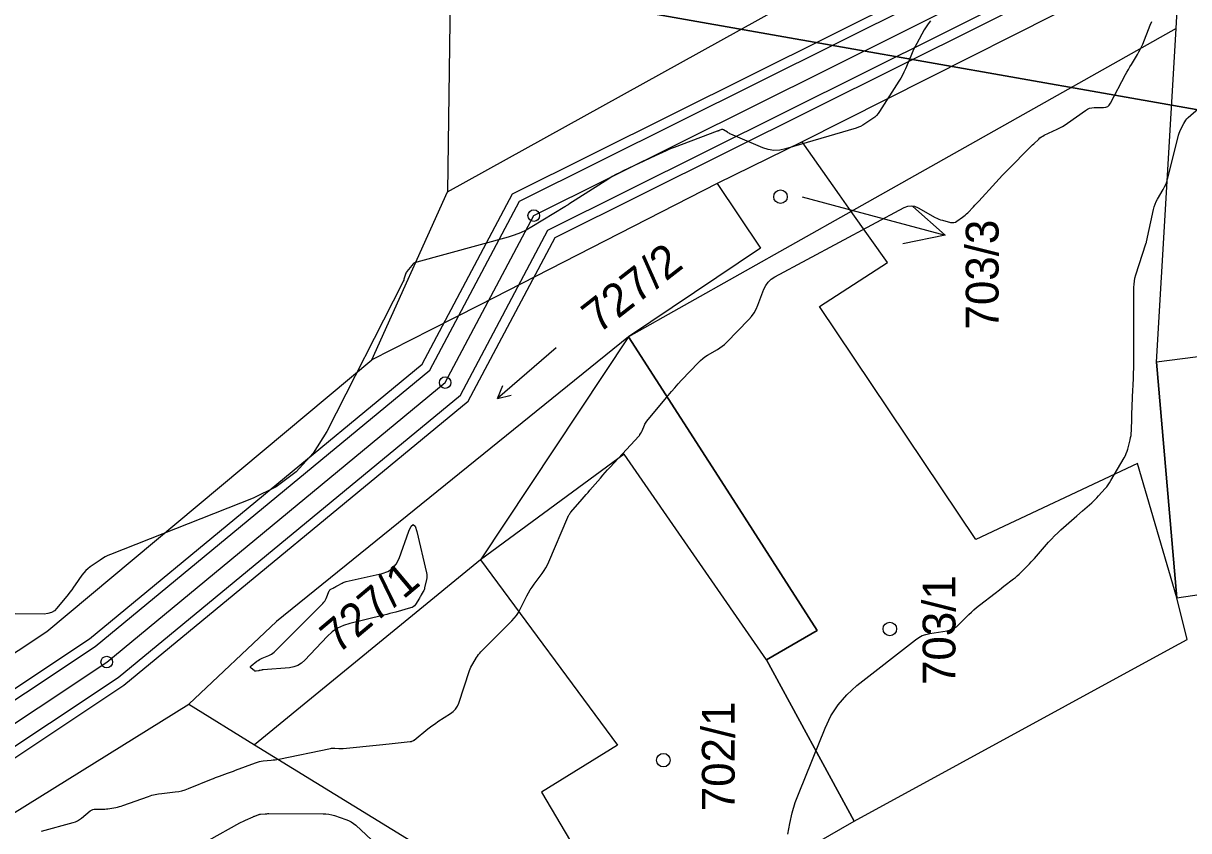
# Model space of a CAD drawing. Extents: x -534481 to -534256, y -1190577 to -1190138.
# Drawn here: x -534395.86 to -534365.66, y -1190377.09 to -1190356.16 of the extents above; entities that cross this region are included whole.
import ezdxf

# ---------------------------------------------------------------- set-up
doc = ezdxf.new("R2010")
doc.units = 0
for name, color, linetype in [('0_kroužky', 7, 'Continuous'), ('30', 7, 'Continuous'), ('31', 7, 'Continuous'), ('_N_osa', 7, 'Continuous'), ('_N_tenká', 7, 'Continuous'), ('_rámeček', 7, 'Continuous'), ('Hranice parcel', 7, 'Continuous'), ('Parcelní čísla', 7, 'Continuous'), ('Polygon budovy', 7, 'Continuous'), ('Pop  PČ popisy', 7, 'Continuous'), ('Značky budov', 7, 'Continuous'), ('Značky kultur', 7, 'Continuous')]:
    doc.layers.add(name, color=color, linetype=linetype)

msp = doc.modelspace()

# ---------------------------------------------------------------- linework, layer by layer
at = {"layer": '0_kroužky'}
for centre in [(-534382.631, -1190361.148), (-534382.631, -1190361.148), (-534382.631, -1190361.148), (-534382.631, -1190361.148), (-534382.631, -1190361.148), (-534382.631, -1190361.148), (-534384.927, -1190365.477), (-534384.927, -1190365.477), (-534384.927, -1190365.477), (-534384.927, -1190365.477), (-534384.927, -1190365.477), (-534384.927, -1190365.477), (-534393.696, -1190372.718), (-534393.696, -1190372.718), (-534393.696, -1190372.718), (-534393.696, -1190372.718), (-534393.696, -1190372.718), (-534393.696, -1190372.718)]:
    msp.add_circle(centre, 0.15, dxfattribs=at)
at = {"layer": '30'}
for points in [[(-534376.046, -1190377.175), (-534375.999, -1190376.898), (-534375.936, -1190376.627), (-534375.856, -1190376.36), (-534375.759, -1190376.097), (-534375.084, -1190374.43), (-534374.933, -1190374.114), (-534374.744, -1190373.825), (-534374.519, -1190373.564), (-534374.257, -1190373.33), (-534372.744, -1190372.141), (-534372.658, -1190372.081), (-534372.567, -1190372.034), (-534372.471, -1190372), (-534372.369, -1190371.977), (-534371.924, -1190371.906), (-534371.837, -1190371.886), (-534371.756, -1190371.852), (-534371.682, -1190371.807), (-534371.615, -1190371.748), (-534371.358, -1190371.488), (-534371.292, -1190371.424), (-534371.225, -1190371.363), (-534371.156, -1190371.304), (-534371.085, -1190371.247), (-534370.679, -1190370.934), (-534370.563, -1190370.845), (-534370.448, -1190370.755), (-534370.201, -1190370.565), (-534370.151, -1190370.525), (-534370.103, -1190370.484), (-534370.056, -1190370.441), (-534370.011, -1190370.397), (-534369.832, -1190370.217), (-534369.788, -1190370.171), (-534369.744, -1190370.125), (-534369.701, -1190370.078), (-534369.659, -1190370.031), (-534369.293, -1190369.615), (-534369.216, -1190369.531), (-534369.138, -1190369.45), (-534369.056, -1190369.371), (-534368.972, -1190369.295), (-534368.557, -1190368.929), (-534368.414, -1190368.802), (-534368.175, -1190368.592), (-534368.128, -1190368.549), (-534368.082, -1190368.505), (-534368.038, -1190368.46), (-534367.995, -1190368.413), (-534367.827, -1190368.222), (-534367.786, -1190368.173), (-534367.748, -1190368.123), (-534367.712, -1190368.07), (-534367.679, -1190368.016), (-534367.332, -1190367.422), (-534367.303, -1190367.369), (-534367.279, -1190367.314), (-534367.258, -1190367.257), (-534367.24, -1190367.199), (-534367.18, -1190366.963), (-534367.166, -1190366.903), (-534367.156, -1190366.844), (-534367.15, -1190366.783), (-534367.146, -1190366.723), (-534367.138, -1190366.388), (-534367.136, -1190366.312), (-534367.133, -1190366.236), (-534367.13, -1190366.16), (-534367.127, -1190366.084), (-534367.105, -1190365.651), (-534367.102, -1190365.571), (-534367.099, -1190365.49), (-534367.096, -1190365.409), (-534367.094, -1190365.329), (-534367.086, -1190365.006), (-534367.084, -1190364.925), (-534367.083, -1190364.844), (-534367.082, -1190364.764), (-534367.082, -1190364.683), (-534367.082, -1190364.349), (-534367.082, -1190364.184), (-534367.082, -1190364.018), (-534367.082, -1190363.671), (-534367.082, -1190363.505), (-534367.082, -1190363.34), (-534367.082, -1190363.01), (-534367.079, -1190362.928), (-534367.069, -1190362.846), (-534367.054, -1190362.766), (-534367.032, -1190362.687), (-534366.773, -1190361.881), (-534366.77, -1190361.872), (-534366.766, -1190361.862), (-534366.757, -1190361.844), (-534366.755, -1190361.839), (-534366.754, -1190361.834), (-534366.752, -1190361.829), (-534366.751, -1190361.825), (-534366.573, -1190360.987), (-534366.555, -1190360.917), (-534366.532, -1190360.849), (-534366.503, -1190360.783), (-534366.469, -1190360.719), (-534366.32, -1190360.468), (-534366.285, -1190360.404), (-534366.255, -1190360.338), (-534366.23, -1190360.27), (-534366.21, -1190360.2), (-534365.935, -1190359.106), (-534365.922, -1190359.06), (-534365.907, -1190359.015), (-534365.89, -1190358.971), (-534365.87, -1190358.928), (-534365.785, -1190358.757), (-534365.762, -1190358.716), (-534365.736, -1190358.678), (-534365.706, -1190358.642), (-534365.672, -1190358.609), (-534365.014, -1190358.03)], [(-534391.053, -1190377.337), (-534390.246, -1190376.885), (-534390.21, -1190376.865), (-534390.173, -1190376.846), (-534390.136, -1190376.829), (-534390.099, -1190376.812), (-534389.905, -1190376.728), (-534389.889, -1190376.721), (-534389.873, -1190376.715), (-534389.857, -1190376.708), (-534389.841, -1190376.702), (-534389.776, -1190376.678), (-534389.759, -1190376.672), (-534389.743, -1190376.667), (-534389.726, -1190376.664), (-534389.708, -1190376.662), (-534389.595, -1190376.651), (-534389.57, -1190376.649), (-534389.545, -1190376.648), (-534389.52, -1190376.647), (-534389.496, -1190376.647), (-534388.092, -1190376.649), (-534388.016, -1190376.652), (-534387.941, -1190376.661), (-534387.866, -1190376.676), (-534387.793, -1190376.698), (-534387.502, -1190376.796), (-534387.431, -1190376.824), (-534387.364, -1190376.858), (-534387.302, -1190376.9), (-534387.243, -1190376.949), (-534386.709, -1190377.445)]]:
    msp.add_lwpolyline(points, dxfattribs=at)
msp.add_lwpolyline([(-534386.285, -1190371.443), (-534386.363, -1190371.463), (-534386.441, -1190371.483), (-534386.519, -1190371.502), (-534387.398, -1190371.715), (-534387.564, -1190371.768), (-534387.718, -1190371.842), (-534387.858, -1190371.939), (-534387.986, -1190372.057), (-534388.565, -1190372.673), (-534388.651, -1190372.749), (-534388.745, -1190372.806), (-534388.849, -1190372.845), (-534388.961, -1190372.864), (-534389.646, -1190372.92), (-534389.656, -1190372.921), (-534389.665, -1190372.923), (-534389.675, -1190372.925), (-534389.685, -1190372.927), (-534389.724, -1190372.936), (-534389.733, -1190372.938), (-534389.743, -1190372.94), (-534389.753, -1190372.942), (-534389.763, -1190372.944), (-534389.828, -1190372.954), (-534389.842, -1190372.955), (-534389.855, -1190372.952), (-534389.867, -1190372.947), (-534389.879, -1190372.939), (-534389.955, -1190372.873), (-534389.967, -1190372.859), (-534389.971, -1190372.845), (-534389.967, -1190372.831), (-534389.954, -1190372.817), (-534389.804, -1190372.698), (-534389.773, -1190372.675), (-534389.74, -1190372.654), (-534389.706, -1190372.636), (-534389.67, -1190372.62), (-534389.5, -1190372.552), (-534389.46, -1190372.534), (-534389.423, -1190372.512), (-534389.389, -1190372.487), (-534389.357, -1190372.458), (-534388.098, -1190371.2), (-534388.071, -1190371.17), (-534388.048, -1190371.138), (-534388.027, -1190371.104), (-534388.01, -1190371.068), (-534387.93, -1190370.875), (-534387.923, -1190370.861), (-534387.913, -1190370.848), (-534387.902, -1190370.838), (-534387.888, -1190370.83), (-534387.816, -1190370.794), (-534387.808, -1190370.79), (-534387.801, -1190370.786), (-534387.794, -1190370.782), (-534387.786, -1190370.778), (-534387.758, -1190370.761), (-534387.743, -1190370.752), (-534387.728, -1190370.744), (-534387.593, -1190370.671), (-534387.568, -1190370.659), (-534387.542, -1190370.648), (-534387.515, -1190370.639), (-534387.488, -1190370.632), (-534386.563, -1190370.425), (-534386.413, -1190370.373), (-534386.289, -1190370.291), (-534386.193, -1190370.179), (-534386.123, -1190370.037), (-534385.866, -1190369.322), (-534385.807, -1190369.194), (-534385.753, -1190369.153), (-534385.705, -1190369.2), (-534385.661, -1190369.334), (-534385.413, -1190370.407), (-534385.405, -1190370.451), (-534385.403, -1190370.494), (-534385.405, -1190370.538), (-534385.412, -1190370.582), (-534385.459, -1190370.796), (-534385.465, -1190370.82), (-534385.473, -1190370.843), (-534385.483, -1190370.866), (-534385.495, -1190370.888), (-534385.545, -1190370.974), (-534385.558, -1190370.996), (-534385.57, -1190371.017), (-534385.583, -1190371.039), (-534385.596, -1190371.06), (-534385.7, -1190371.226), (-534385.724, -1190371.258), (-534385.752, -1190371.284), (-534385.785, -1190371.303), (-534385.822, -1190371.317), (-534386.208, -1190371.422)], close=True, dxfattribs=at)
at = {"layer": '31'}
for points in [[(-534372.349, -1190356.102), (-534372.408, -1190356.177), (-534372.463, -1190356.256), (-534372.512, -1190356.338), (-534372.706, -1190356.686), (-534372.749, -1190356.766), (-534372.789, -1190356.847), (-534372.828, -1190356.929), (-534372.864, -1190357.012), (-534373.003, -1190357.347), (-534373.04, -1190357.43), (-534373.08, -1190357.511), (-534373.124, -1190357.59), (-534373.171, -1190357.667), (-534373.675, -1190358.453), (-534373.711, -1190358.504), (-534373.752, -1190358.55), (-534373.797, -1190358.593), (-534373.847, -1190358.631), (-534374.055, -1190358.773), (-534374.109, -1190358.807), (-534374.164, -1190358.836), (-534374.221, -1190358.86), (-534374.281, -1190358.88), (-534376.108, -1190359.422), (-534376.258, -1190359.453), (-534376.407, -1190359.458), (-534376.554, -1190359.436), (-534376.7, -1190359.388), (-534377.524, -1190359.037), (-534377.547, -1190359.027), (-534377.57, -1190359.015), (-534377.592, -1190359.003), (-534377.614, -1190358.99), (-534377.718, -1190358.923), (-534377.731, -1190358.917), (-534377.744, -1190358.915), (-534377.757, -1190358.915), (-534377.77, -1190358.919), (-534377.824, -1190358.941), (-534377.838, -1190358.947), (-534377.851, -1190358.952), (-534377.865, -1190358.958), (-534377.879, -1190358.963), (-534378.994, -1190359.382), (-534379.071, -1190359.411), (-534379.147, -1190359.443), (-534379.222, -1190359.475), (-534379.297, -1190359.51), (-534379.594, -1190359.651), (-534379.669, -1190359.686), (-534379.743, -1190359.721), (-534379.818, -1190359.756), (-534379.892, -1190359.791), (-534380.317, -1190359.99), (-534380.412, -1190360.036), (-534380.505, -1190360.085), (-534380.597, -1190360.137), (-534380.687, -1190360.192), (-534381.726, -1190360.854), (-534381.735, -1190360.859), (-534381.743, -1190360.865), (-534381.751, -1190360.87), (-534381.76, -1190360.876), (-534381.793, -1190360.899), (-534381.801, -1190360.905), (-534381.81, -1190360.911), (-534381.818, -1190360.916), (-534381.827, -1190360.921), (-534382.679, -1190361.441), (-534382.827, -1190361.524), (-534382.979, -1190361.597), (-534383.135, -1190361.658), (-534383.297, -1190361.708), (-534385.662, -1190362.352), (-534385.701, -1190362.366), (-534385.736, -1190362.385), (-534385.767, -1190362.41), (-534385.795, -1190362.44), (-534385.917, -1190362.595), (-534385.933, -1190362.617), (-534385.946, -1190362.639), (-534385.957, -1190362.664), (-534385.965, -1190362.689), (-534385.995, -1190362.793), (-534386.002, -1190362.818), (-534386.012, -1190362.844), (-534386.022, -1190362.868), (-534386.034, -1190362.892), (-534387.997, -1190366.74), (-534388.35, -1190367.307), (-534388.786, -1190367.785), (-534389.303, -1190368.173), (-534389.902, -1190368.47), (-534393.6, -1190369.929), (-534393.67, -1190369.959), (-534393.739, -1190369.993), (-534393.805, -1190370.032), (-534393.869, -1190370.074), (-534394.122, -1190370.251), (-534394.183, -1190370.298), (-534394.239, -1190370.349), (-534394.29, -1190370.405), (-534394.337, -1190370.466), (-534394.514, -1190370.718), (-534394.558, -1190370.781), (-534394.604, -1190370.843), (-534394.651, -1190370.904), (-534394.699, -1190370.964), (-534394.985, -1190371.318), (-534395.053, -1190371.387), (-534395.131, -1190371.436), (-534395.218, -1190371.464), (-534395.315, -1190371.473), (-534405.894, -1190371.358)], [(-534395.39, -1190377.105), (-534394.568, -1190376.878), (-534394.509, -1190376.858), (-534394.453, -1190376.833), (-534394.401, -1190376.802), (-534394.351, -1190376.765), (-534394.123, -1190376.577), (-534394.091, -1190376.555), (-534394.057, -1190376.539), (-534394.02, -1190376.53), (-534393.982, -1190376.528), (-534393.823, -1190376.531), (-534393.783, -1190376.531), (-534393.743, -1190376.529), (-534393.704, -1190376.525), (-534393.665, -1190376.519), (-534393.462, -1190376.485), (-534393.415, -1190376.476), (-534393.369, -1190376.465), (-534393.323, -1190376.452), (-534393.278, -1190376.437), (-534392.614, -1190376.2), (-534392.53, -1190376.172), (-534392.445, -1190376.15), (-534392.359, -1190376.133), (-534392.271, -1190376.121), (-534391.919, -1190376.084), (-534391.832, -1190376.071), (-534391.746, -1190376.053), (-534391.662, -1190376.029), (-534391.579, -1190375.998), (-534390.979, -1190375.752), (-534390.928, -1190375.732), (-534390.877, -1190375.712), (-534390.825, -1190375.692), (-534390.773, -1190375.674), (-534390.565, -1190375.6), (-534390.513, -1190375.581), (-534390.461, -1190375.562), (-534390.41, -1190375.543), (-534390.358, -1190375.524), (-534389.839, -1190375.327), (-534389.791, -1190375.31), (-534389.742, -1190375.297), (-534389.692, -1190375.287), (-534389.641, -1190375.281), (-534389.437, -1190375.262), (-534389.386, -1190375.256), (-534389.336, -1190375.249), (-534389.285, -1190375.241), (-534389.235, -1190375.232), (-534387.895, -1190374.955), (-534387.869, -1190374.95), (-534387.842, -1190374.948), (-534387.815, -1190374.947), (-534387.788, -1190374.948), (-534387.68, -1190374.957), (-534387.653, -1190374.958), (-534387.627, -1190374.959), (-534387.6, -1190374.958), (-534387.573, -1190374.956), (-534386.626, -1190374.861), (-534386.544, -1190374.853), (-534386.463, -1190374.844), (-534386.382, -1190374.836), (-534386.3, -1190374.827), (-534385.83, -1190374.778), (-534385.821, -1190374.777), (-534385.812, -1190374.775), (-534385.803, -1190374.773), (-534385.794, -1190374.77), (-534385.76, -1190374.758), (-534385.752, -1190374.754), (-534385.744, -1190374.75), (-534385.736, -1190374.746), (-534385.729, -1190374.74), (-534385.372, -1190374.45), (-534385.309, -1190374.401), (-534385.245, -1190374.353), (-534385.18, -1190374.307), (-534385.114, -1190374.263), (-534384.787, -1190374.053), (-534384.716, -1190373.999), (-534384.657, -1190373.936), (-534384.61, -1190373.863), (-534384.575, -1190373.781), (-534384.293, -1190372.934), (-534384.276, -1190372.89), (-534384.258, -1190372.847), (-534384.237, -1190372.805), (-534384.213, -1190372.764), (-534384.115, -1190372.603), (-534384.089, -1190372.563), (-534384.061, -1190372.526), (-534384.031, -1190372.49), (-534383.999, -1190372.455), (-534383.202, -1190371.652), (-534383.139, -1190371.583), (-534383.081, -1190371.51), (-534383.03, -1190371.432), (-534382.984, -1190371.35), (-534382.807, -1190371.001), (-534382.766, -1190370.924), (-534382.722, -1190370.848), (-534382.674, -1190370.775), (-534382.623, -1190370.703), (-534382.414, -1190370.42), (-534382.364, -1190370.348), (-534382.318, -1190370.273), (-534382.277, -1190370.196), (-534382.24, -1190370.117), (-534381.75, -1190368.962), (-534381.746, -1190368.953), (-534381.742, -1190368.945), (-534381.738, -1190368.937), (-534381.733, -1190368.929), (-534381.71, -1190368.893), (-534381.704, -1190368.883), (-534381.699, -1190368.874), (-534381.688, -1190368.854), (-534381.685, -1190368.849), (-534381.682, -1190368.845), (-534381.679, -1190368.84), (-534381.675, -1190368.836), (-534381.378, -1190368.495), (-534381.328, -1190368.437), (-534381.277, -1190368.378), (-534381.226, -1190368.32), (-534381.176, -1190368.262), (-534380.905, -1190367.949), (-534380.843, -1190367.878), (-534380.78, -1190367.807), (-534380.717, -1190367.737), (-534380.653, -1190367.667), (-534379.912, -1190366.865), (-534379.903, -1190366.854), (-534379.894, -1190366.844), (-534379.886, -1190366.833), (-534379.879, -1190366.821), (-534379.85, -1190366.775), (-534379.843, -1190366.764), (-534379.836, -1190366.752), (-534379.831, -1190366.739), (-534379.825, -1190366.727), (-534379.766, -1190366.58), (-534379.754, -1190366.552), (-534379.739, -1190366.525), (-534379.722, -1190366.499), (-534379.704, -1190366.475), (-534379.149, -1190365.807), (-534379.065, -1190365.707), (-534378.979, -1190365.608), (-534378.891, -1190365.511), (-534378.802, -1190365.415), (-534378.365, -1190364.953), (-534378.312, -1190364.901), (-534378.255, -1190364.853), (-534378.196, -1190364.809), (-534378.132, -1190364.769), (-534377.873, -1190364.618), (-534377.81, -1190364.579), (-534377.749, -1190364.535), (-534377.692, -1190364.487), (-534377.638, -1190364.435), (-534377.062, -1190363.843), (-534376.988, -1190363.759), (-534376.925, -1190363.67), (-534376.871, -1190363.574), (-534376.826, -1190363.473), (-534376.666, -1190363.054), (-534376.619, -1190362.956), (-534376.557, -1190362.87), (-534376.481, -1190362.798), (-534376.389, -1190362.739), (-534373.032, -1190360.941), (-534372.942, -1190360.905), (-534372.853, -1190360.893), (-534372.764, -1190360.907), (-534372.675, -1190360.944), (-534372.232, -1190361.193), (-534372.187, -1190361.217), (-534372.14, -1190361.238), (-534372.092, -1190361.255), (-534372.043, -1190361.269), (-534371.83, -1190361.323), (-534371.788, -1190361.33), (-534371.746, -1190361.327), (-534371.707, -1190361.315), (-534371.669, -1190361.294), (-534371.522, -1190361.191), (-534371.486, -1190361.164), (-534371.452, -1190361.135), (-534371.419, -1190361.105), (-534371.387, -1190361.074), (-534371.24, -1190360.918), (-534371.205, -1190360.881), (-534371.17, -1190360.844), (-534371.136, -1190360.807), (-534371.101, -1190360.77), (-534370.656, -1190360.288), (-534370.57, -1190360.196), (-534370.483, -1190360.104), (-534370.396, -1190360.013), (-534370.308, -1190359.923), (-534369.805, -1190359.411), (-534369.774, -1190359.38), (-534369.742, -1190359.349), (-534369.71, -1190359.318), (-534369.678, -1190359.287), (-534369.548, -1190359.165), (-534369.515, -1190359.136), (-534369.479, -1190359.11), (-534369.442, -1190359.087), (-534369.403, -1190359.067), (-534369.066, -1190358.909), (-534368.997, -1190358.875), (-534368.93, -1190358.838), (-534368.865, -1190358.798), (-534368.802, -1190358.755), (-534368.338, -1190358.422), (-534368.286, -1190358.391), (-534368.231, -1190358.368), (-534368.174, -1190358.354), (-534368.114, -1190358.349), (-534367.867, -1190358.346), (-534367.809, -1190358.339), (-534367.76, -1190358.318), (-534367.719, -1190358.283), (-534367.686, -1190358.235), (-534367.297, -1190357.495), (-534367.261, -1190357.428), (-534367.225, -1190357.362), (-534367.187, -1190357.297), (-534367.147, -1190357.232), (-534366.989, -1190356.974), (-534366.95, -1190356.908), (-534366.915, -1190356.841), (-534366.883, -1190356.773), (-534366.854, -1190356.703), (-534366.664, -1190356.215), (-534366.617, -1190356.115)]]:
    msp.add_lwpolyline(points, dxfattribs=at)
at = {"layer": '_N_osa'}
msp.add_lwpolyline([(-534409.868, -1190391.439), (-534405.947, -1190382.816), (-534400.873, -1190377.487), (-534393.696, -1190372.718), (-534384.927, -1190365.477), (-534382.631, -1190361.148), (-534355.894, -1190347.823), (-534351.738, -1190342.389), (-534351.577, -1190328.316), (-534347.204, -1190300.921), (-534345.553, -1190283.64), (-534344.682, -1190264.494)], dxfattribs=at)
at = {"layer": '_N_tenká'}
for points in [[(-534409.916, -1190390.337), (-534406.368, -1190382.532), (-534401.196, -1190377.102), (-534393.995, -1190372.316), (-534385.322, -1190365.155), (-534382.997, -1190360.772), (-534356.221, -1190347.427), (-534352.236, -1190342.217), (-534352.076, -1190328.274), (-534347.7, -1190300.857), (-534346.052, -1190283.605), (-534345.255, -1190266.096)], [(-534409.879, -1190389.652), (-534406.578, -1190382.39), (-534401.358, -1190376.909), (-534394.144, -1190372.115), (-534385.52, -1190364.994), (-534383.181, -1190360.584), (-534356.384, -1190347.229), (-534352.485, -1190342.131), (-534352.326, -1190328.253), (-534347.948, -1190300.826), (-534346.301, -1190283.588), (-534345.507, -1190266.125)], [(-534409.363, -1190391.537), (-534405.527, -1190383.099), (-534400.549, -1190377.873), (-534393.398, -1190373.12), (-534384.532, -1190365.799), (-534382.264, -1190361.524), (-534355.568, -1190348.219), (-534351.24, -1190342.56), (-534351.077, -1190328.359), (-534346.708, -1190300.984), (-534345.054, -1190283.675), (-534344.256, -1190266.142)], [(-534409.111, -1190391.586), (-534405.317, -1190383.241), (-534400.388, -1190378.065), (-534393.249, -1190373.321), (-534384.335, -1190365.96), (-534382.081, -1190361.712), (-534355.404, -1190348.417), (-534350.991, -1190342.646), (-534350.828, -1190328.38), (-534346.46, -1190301.016), (-534344.805, -1190283.693), (-534344.008, -1190266.196)]]:
    msp.add_lwpolyline(points, dxfattribs=at)
at = {"layer": '_rámeček'}
for points in [[(-534333.072, -1190257.49), (-534426.145, -1190241.079), (-534444.378, -1190344.484), (-534298.134, -1190370.27)], [(-534298.134, -1190370.27), (-534444.378, -1190344.484), (-534462.611, -1190447.888), (-534316.367, -1190473.675)]]:
    msp.add_lwpolyline(points, dxfattribs=at)
at = {"layer": 'Hranice parcel'}
for p, q in [((-534384.75, -1190352.48), (-534384.87, -1190360.53)), ((-534365.99, -1190356.3), (-534365.87, -1190354.29)), ((-534384.87, -1190360.53), (-534374.45, -1190354.76)), ((-534386.83, -1190364.89), (-534384.87, -1190360.53)), ((-534365.97, -1190371.05), (-534357.17, -1190369.75)), ((-534391.57, -1190373.81), (-534389.87, -1190374.86))]:
    msp.add_line(p, q, dxfattribs=at)
for points in [[(-534365.87, -1190354.29), (-534375.68, -1190359.24), (-534377.88, -1190360.32)], [(-534365.99, -1190356.3), (-534374.41, -1190361.04), (-534380.18, -1190364.29)], [(-534365.97, -1190371.05), (-534366.5, -1190364.95), (-534365.99, -1190356.3)], [(-534377.88, -1190360.32), (-534384.04, -1190363.47), (-534385.3, -1190364.11), (-534386.83, -1190364.89)], [(-534377.88, -1190360.32), (-534376.76, -1190361.99), (-534380.18, -1190364.29)], [(-534380.18, -1190364.29), (-534389.3, -1190371.67), (-534391.57, -1190373.81)], [(-534380.18, -1190364.29), (-534384.01, -1190370.07), (-534389.87, -1190374.86)], [(-534374.33, -1190376.84), (-534376.6, -1190372.66), (-534375.29, -1190371.9), (-534377.39, -1190368.63), (-534380.18, -1190364.29)], [(-534407.69, -1190381.54), (-534401.89, -1190376.32), (-534395.25, -1190371.93), (-534386.83, -1190364.89)], [(-534374.33, -1190376.84), (-534366.12, -1190372.36), (-534365.7, -1190372.13), (-534365.97, -1190371.05)], [(-534402.36, -1190381.41), (-534399.95, -1190379.17), (-534397.88, -1190377.73), (-534391.57, -1190373.81)], [(-534389.87, -1190374.86), (-534381.65, -1190379.91), (-534381.11, -1190380.27)], [(-534381.11, -1190380.27), (-534380.34, -1190379.62), (-534380.04, -1190380.12), (-534376.63, -1190378.16), (-534374.33, -1190376.84)]]:
    msp.add_lwpolyline(points, dxfattribs=at)
at = {"layer": 'Polygon budovy'}
for points in [[(-534366.5, -1190364.95), (-534365.97, -1190371.05), (-534357.17, -1190369.75), (-534356.84, -1190364.64), (-534356.15, -1190355.55), (-534355.88, -1190351.91), (-534359.93, -1190352.28), (-534360.28, -1190356.91), (-534360.12, -1190356.93), (-534360.9, -1190364.23)], [(-534374.41, -1190361.04), (-534374.71, -1190360.61), (-534375.68, -1190359.24), (-534377.88, -1190360.32), (-534376.76, -1190361.99), (-534380.18, -1190364.29), (-534377.39, -1190368.63), (-534375.29, -1190371.9), (-534376.6, -1190372.66), (-534374.33, -1190376.84), (-534366.12, -1190372.36), (-534365.7, -1190372.13), (-534365.97, -1190371.05), (-534366.99, -1190367.57), (-534371.18, -1190369.54), (-534375.23, -1190363.5), (-534373.47, -1190362.36)], [(-534380.29, -1190367.33), (-534384.01, -1190370.07), (-534380.46, -1190374.87), (-534382.43, -1190376.09), (-534380.34, -1190379.62), (-534380.04, -1190380.12), (-534376.63, -1190378.16), (-534374.33, -1190376.84), (-534376.6, -1190372.66)]]:
    msp.add_lwpolyline(points, close=True, dxfattribs=at)
at = {"layer": 'Pop  PČ popisy'}
for p, q in [((-534375.68, -1190360.66), (-534374.87, -1190360.88)), ((-534374.87, -1190360.88), (-534371.971, -1190361.657)), ((-534371.971, -1190361.657), (-534372.809, -1190360.914)), ((-534371.971, -1190361.657), (-534373.068, -1190361.881))]:
    msp.add_line(p, q, dxfattribs=at)
at = {"layer": 'Značky budov'}
for centre in [(-534376.237, -1190360.659), (-534373.405, -1190371.86), (-534379.273, -1190375.262)]:
    msp.add_circle(centre, 0.175, dxfattribs=at)
at = {"layer": 'Značky kultur'}
for p, q in [((-534382.055, -1190364.574), (-534383.572, -1190365.892)), ((-534383.572, -1190365.892), (-534383.436, -1190365.551)), ((-534383.572, -1190365.892), (-534383.215, -1190365.804))]:
    msp.add_line(p, q, dxfattribs=at)

# ---------------------------------------------------------------- texts
at = {"layer": 'Parcelní čísla'}
for s, rotation, p in [('703/3', 90, (-534370.588, -1190364.099)), ('727/2', 37.9667, (-534380.955, -1190364.227)), ('727/1', 40, (-534387.709, -1190372.531)), ('703/1', 90, (-534371.705, -1190373.312)), ('702/1', 90, (-534377.425, -1190376.584))]:
    msp.add_text(s, height=0.85, rotation=rotation, dxfattribs=at).set_placement(p)

doc.saveas('drawing.dxf')
